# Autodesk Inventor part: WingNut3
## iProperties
Author: Administrator
Shininess: 25.0
PropertySet Name: _Private Model Information
Created: 2001-02
Part Number: WingNut3
Document SubType Name: Modeling
Designer: Administrator
Material: Steel, Mild
Control State: 0
Master: False
Checked Out: False
PropertySet Name: Design Tracking Control
Density: 7.859999999999999
Volumn: 1.7084661058746171
Area: 24.90891926502218
PropertySet Name: Model Information
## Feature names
1. Extrusion1
2. Extrusion2
3. Fillet1
4. Fillet2
5. Shell1
